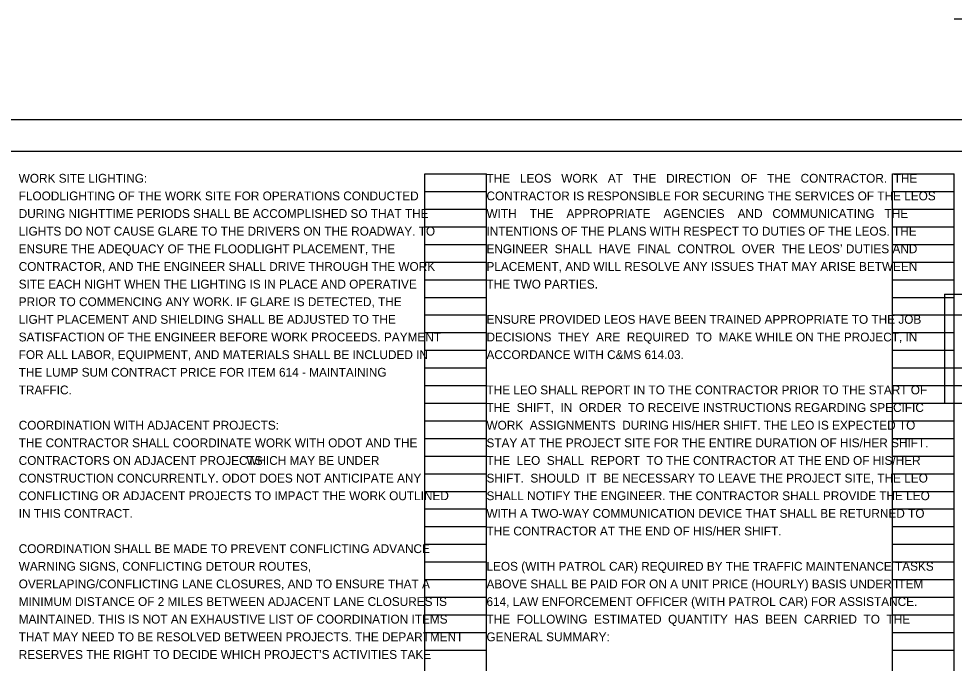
# Model space of a CAD drawing. Extents: x -7.9 to 64.5, y -13.1 to 23.6.
# Drawn here: x 2.4 to 17.24, y 13.37 to 23.6 of the extents above; entities that cross this region are included whole.
import ezdxf

# ---------------------------------------------------------------- set-up
doc = ezdxf.new("R2010")
doc.units = 0
for name, color, linetype in [('SH_Border', 7, 'Continuous'), ('SH_Cut_Line', 7, 'Continuous'), ('SH_Data', 7, 'Continuous'), ('SH_Text', 7, 'Continuous')]:
    doc.layers.add(name, color=color, linetype=linetype)

msp = doc.modelspace()

# ---------------------------------------------------------------- linework, layer by layer
at = {"layer": 'SH_Border'}
msp.add_lwpolyline([(1.5, 21.5), (33.5, 21.5), (33.5, 0.5), (1.5, 0.5)], close=True, dxfattribs=at)
at = {"layer": 'SH_Cut_Line'}
msp.add_lwpolyline([(0, 0), (34, 0), (34, 22), (0, 22)], close=True, dxfattribs=at)
at = {"layer": 'SH_Data'}
for p, q in [((8.84, 0.98), (8.84, 21.14)), ((8.84, 21.14), (9.82, 21.14)), ((9.82, 0.98), (9.82, 21.14)), ((16.26, 0.98), (16.26, 21.14)), ((16.26, 21.14), (17.24, 21.14)), ((17.24, 0.98), (17.24, 21.14)), ((8.84, 20.86), (9.82, 20.86)), ((16.26, 20.86), (17.24, 20.86)), ((8.84, 20.58), (9.82, 20.58)), ((16.26, 20.58), (17.24, 20.58)), ((8.84, 20.3), (9.82, 20.3)), ((16.26, 20.3), (17.24, 20.3)), ((8.84, 20.02), (9.82, 20.02)), ((16.26, 20.02), (17.24, 20.02)), ((8.84, 19.74), (9.82, 19.74)), ((16.26, 19.74), (17.24, 19.74)), ((8.84, 19.46), (9.82, 19.46)), ((16.26, 19.46), (17.24, 19.46)), ((8.84, 19.18), (9.82, 19.18)), ((16.26, 19.18), (17.24, 19.18)), ((8.84, 18.9), (9.82, 18.9)), ((16.26, 18.9), (17.24, 18.9)), ((8.84, 18.62), (9.82, 18.62)), ((16.26, 18.62), (17.24, 18.62)), ((8.84, 18.34), (9.82, 18.34)), ((16.26, 18.34), (17.24, 18.34)), ((8.84, 18.06), (9.82, 18.06)), ((16.26, 18.06), (17.24, 18.06)), ((8.84, 17.78), (9.82, 17.78)), ((16.26, 17.78), (17.24, 17.78)), ((8.84, 17.5), (9.82, 17.5)), ((16.26, 17.5), (17.24, 17.5)), ((8.84, 17.22), (9.82, 17.22)), ((16.26, 17.22), (17.24, 17.22)), ((8.84, 16.94), (9.82, 16.94)), ((16.26, 16.94), (17.24, 16.94)), ((8.84, 16.66), (9.82, 16.66)), ((16.26, 16.66), (17.24, 16.66)), ((8.84, 16.38), (9.82, 16.38)), ((16.26, 16.38), (17.24, 16.38)), ((8.84, 16.1), (9.82, 16.1)), ((16.26, 16.1), (17.24, 16.1)), ((8.84, 15.82), (9.82, 15.82)), ((16.26, 15.82), (17.24, 15.82)), ((8.84, 15.54), (9.82, 15.54)), ((16.26, 15.54), (17.24, 15.54)), ((8.84, 15.26), (9.82, 15.26)), ((16.26, 15.26), (17.24, 15.26)), ((8.84, 14.98), (9.82, 14.98)), ((16.26, 14.98), (17.24, 14.98)), ((8.84, 14.7), (9.82, 14.7)), ((16.26, 14.7), (17.24, 14.7)), ((8.84, 14.42), (9.82, 14.42)), ((16.26, 14.42), (17.24, 14.42)), ((8.84, 14.14), (9.82, 14.14)), ((16.26, 14.14), (17.24, 14.14)), ((8.84, 13.86), (9.82, 13.86)), ((16.26, 13.86), (17.24, 13.86)), ((8.84, 13.58), (9.82, 13.58)), ((16.26, 13.58), (17.24, 13.58))]:
    msp.add_line(p, q, dxfattribs=at)
at = {"layer": 'SH_Text'}
for p, q in [((17.24, 23.604), (23.68, 23.604)), ((17.084, 19.229), (23.836, 19.229)), ((17.084, 19.229), (17.084, 17.5)), ((17.084, 18.9), (23.836, 18.9)), ((17.084, 18.06), (23.836, 18.06)), ((17.084, 17.78), (23.836, 17.78)), ((17.084, 17.5), (23.836, 17.5))]:
    msp.add_line(p, q, dxfattribs=at)

# ---------------------------------------------------------------- texts
for s, p in [('WORK SITE LIGHTING:', (2.4, 21)), ('THE   LEOS   WORK   AT   THE   DIRECTION   OF   THE   CONTRACTOR.  THE', (9.82, 21)), ('FLOODLIGHTING OF THE WORK SITE FOR OPERATIONS CONDUCTED ', (2.4, 20.72)), ('CONTRACTOR IS RESPONSIBLE FOR SECURING THE SERVICES OF THE LEOS', (9.82, 20.72)), ('DURING NIGHTTIME PERIODS SHALL BE ACCOMPLISHED SO THAT THE ', (2.4, 20.44)), ('WITH    THE    APPROPRIATE    AGENCIES    AND   COMMUNICATING   THE', (9.82, 20.44)), ('LIGHTS DO NOT CAUSE GLARE TO THE DRIVERS ON THE ROADWAY. TO ', (2.4, 20.16)), ('INTENTIONS OF THE PLANS WITH RESPECT TO DUTIES OF THE LEOS. THE', (9.82, 20.16)), ('ENSURE THE ADEQUACY OF THE FLOODLIGHT PLACEMENT, THE ', (2.4, 19.88)), ('ENGINEER  SHALL  HAVE  FINAL  CONTROL  OVER  THE LEOS’ DUTIES AND', (9.82, 19.88)), ('CONTRACTOR, AND THE ENGINEER SHALL DRIVE THROUGH THE WORK ', (2.4, 19.6)), ('PLACEMENT, AND WILL RESOLVE ANY ISSUES THAT MAY ARISE BETWEEN', (9.82, 19.6)), ('SITE EACH NIGHT WHEN THE LIGHTING IS IN PLACE AND OPERATIVE ', (2.4, 19.32)), ('THE TWO PARTIES.', (9.82, 19.32)), ('PRIOR TO COMMENCING ANY WORK. IF GLARE IS DETECTED, THE ', (2.4, 19.04)), ('LIGHT PLACEMENT AND SHIELDING SHALL BE ADJUSTED TO THE ', (2.4, 18.76)), ('ENSURE PROVIDED LEOS HAVE BEEN TRAINED APPROPRIATE TO THE JOB', (9.82, 18.76)), ('SATISFACTION OF THE ENGINEER BEFORE WORK PROCEEDS. PAYMENT ', (2.4, 18.48)), ('DECISIONS  THEY  ARE  REQUIRED  TO  MAKE WHILE ON THE PROJECT, IN', (9.82, 18.48)), ('FOR ALL LABOR, EQUIPMENT, AND MATERIALS SHALL BE INCLUDED IN ', (2.4, 18.2)), ('ACCORDANCE WITH C&MS 614.03.', (9.82, 18.2)), ('THE LUMP SUM CONTRACT PRICE FOR ITEM 614 - MAINTAINING ', (2.4, 17.92)), ('TRAFFIC.', (2.4, 17.64)), ('THE LEO SHALL REPORT IN TO THE CONTRACTOR PRIOR TO THE START OF', (9.82, 17.64)), ('THE  SHIFT,  IN  ORDER  TO RECEIVE INSTRUCTIONS REGARDING SPECIFIC', (9.82, 17.36)), ('COORDINATION WITH ADJACENT PROJECTS:', (2.4, 17.08)), ('WORK  ASSIGNMENTS  DURING HIS/HER SHIFT. THE LEO IS EXPECTED TO', (9.82, 17.08)), ('THE CONTRACTOR SHALL COORDINATE WORK WITH ODOT AND THE ', (2.4, 16.8)), ('STAY AT THE PROJECT SITE FOR THE ENTIRE DURATION OF HIS/HER SHIFT.', (9.82, 16.8)), ('CONTRACTORS ON ADJACENT PROJECTS', (2.4, 16.52)), (' WHICH MAY BE UNDER ', (5.958, 16.52)), ('THE  LEO  SHALL  REPORT  TO THE CONTRACTOR AT THE END OF HIS/HER', (9.82, 16.52)), ('CONSTRUCTION CONCURRENTLY. ODOT DOES NOT ANTICIPATE ANY ', (2.4, 16.24)), ('SHIFT.  SHOULD  IT  BE NECESSARY TO LEAVE THE PROJECT SITE, THE LEO', (9.82, 16.24)), ('CONFLICTING OR ADJACENT PROJECTS TO IMPACT THE WORK OUTLINED ', (2.4, 15.96)), ('SHALL NOTIFY THE ENGINEER. THE CONTRACTOR SHALL PROVIDE THE LEO', (9.82, 15.96)), ('IN THIS CONTRACT.', (2.4, 15.68)), ('WITH A TWO-WAY COMMUNICATION DEVICE THAT SHALL BE RETURNED TO', (9.82, 15.68)), ('THE CONTRACTOR AT THE END OF HIS/HER SHIFT.', (9.82, 15.4)), ('COORDINATION SHALL BE MADE TO PREVENT CONFLICTING ADVANCE ', (2.4, 15.12)), ('WARNING SIGNS, CONFLICTING DETOUR ROUTES, ', (2.4, 14.84)), ('LEOS (WITH PATROL CAR) REQUIRED BY THE TRAFFIC MAINTENANCE TASKS', (9.82, 14.84)), ('OVERLAPING/CONFLICTING LANE CLOSURES, AND TO ENSURE THAT A ', (2.4, 14.56)), ('ABOVE SHALL BE PAID FOR ON A UNIT PRICE (HOURLY) BASIS UNDER ITEM', (9.82, 14.56)), ('MINIMUM DISTANCE OF 2 MILES BETWEEN ADJACENT LANE CLOSURES IS ', (2.4, 14.28)), ('614, LAW ENFORCEMENT OFFICER (WITH PATROL CAR) FOR ASSISTANCE.', (9.82, 14.28)), ('MAINTAINED. THIS IS NOT AN EXHAUSTIVE LIST OF COORDINATION ITEMS ', (2.4, 14)), ('THE  FOLLOWING  ESTIMATED  QUANTITY  HAS  BEEN  CARRIED  TO  THE', (9.82, 14)), ('THAT MAY NEED TO BE RESOLVED BETWEEN PROJECTS. THE DEPARTMENT ', (2.4, 13.72)), ('GENERAL SUMMARY:', (9.82, 13.72)), ('RESERVES THE RIGHT TO DECIDE WHICH PROJECT’S ACTIVITIES TAKE ', (2.4, 13.44))]:
    msp.add_text(s, height=0.14, dxfattribs=at).set_placement(p)

doc.saveas('drawing.dxf')
